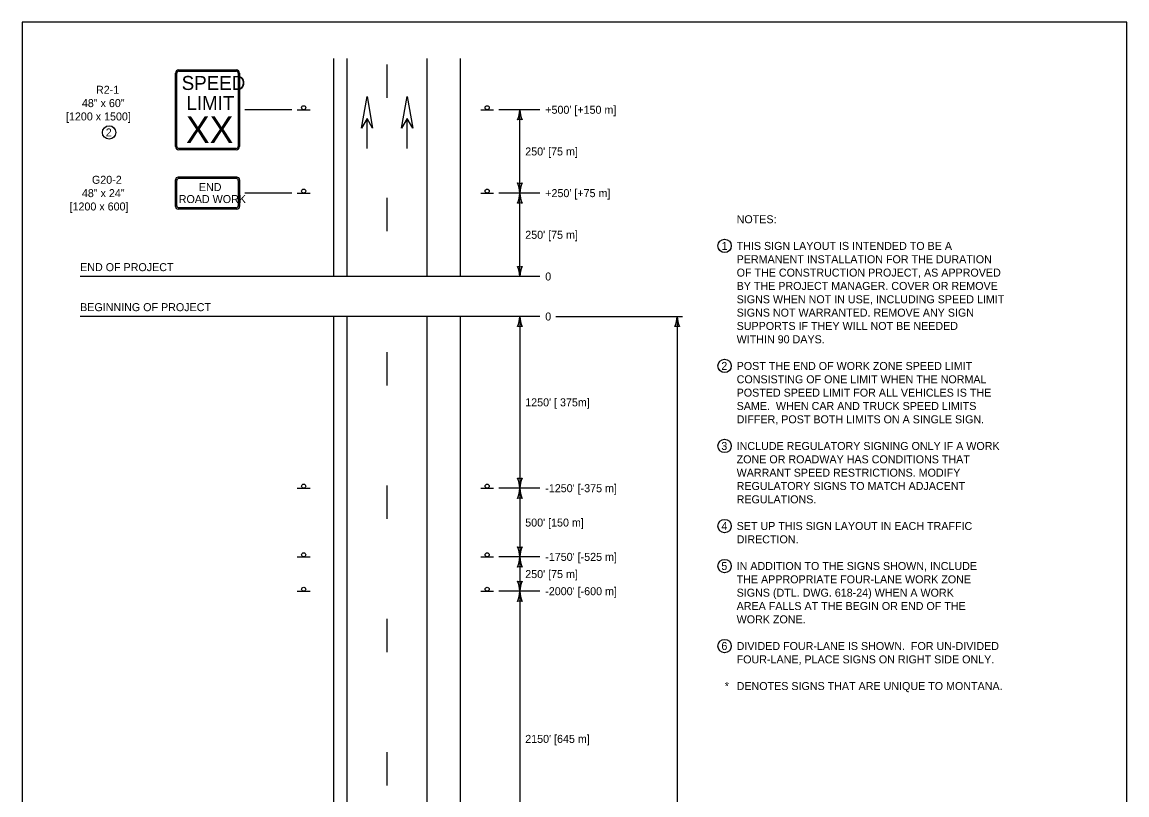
# Model space of a CAD drawing. Extents: x 49991.4 to 50021, y 49987.6 to 50011.4.
# Drawn here: x 50000.34 to 50008.61, y 50005.47 to 50011.26 of the extents above; entities that cross this region are included whole.
import ezdxf

# ---------------------------------------------------------------- set-up
doc = ezdxf.new("R2010")
doc.units = 0
for name, color, linetype in [('Level 1', 7, 'Continuous'), ('Level 2', 7, 'Continuous'), ('Level 3', 7, 'Continuous')]:
    doc.layers.add(name, color=color, linetype=linetype)

msp = doc.modelspace()

# ---------------------------------------------------------------- linework, layer by layer
at = {"layer": 'Level 1'}
for p, q in [((50002.6707, 50009.3553), (50002.6707, 50010.9901)), ((50002.7707, 50009.3553), (50002.7707, 50010.9901)), ((50003.3707, 50009.3553), (50003.3707, 50010.9901)), ((50003.6207, 50009.3553), (50003.6207, 50010.9901)), ((50001.4852, 50010.3303), (50001.4852, 50010.8803)), ((50001.4952, 50010.3303), (50001.4952, 50010.8803)), ((50001.5102, 50010.9053), (50001.9402, 50010.9053)), ((50001.5102, 50010.8953), (50001.9402, 50010.8953)), ((50001.9552, 50010.8803), (50001.9552, 50010.3303)), ((50001.9652, 50010.8803), (50001.9652, 50010.3303)), ((50003.0707, 50010.6959), (50003.0707, 50010.9459)), ((50002.3977, 50010.6053), (50002.4937, 50010.6053)), ((50003.7727, 50010.6053), (50003.8687, 50010.6053)), ((50002.9207, 50010.3139), (50002.9207, 50010.5398)), ((50002.921, 50010.3139), (50002.921, 50010.5398)), ((50003.2207, 50010.3139), (50003.2207, 50010.5398)), ((50003.221, 50010.3139), (50003.221, 50010.5398)), ((50001.9402, 50010.3153), (50001.5102, 50010.3153)), ((50001.9402, 50010.3053), (50001.5102, 50010.3053)), ((50001.4852, 50009.8803), (50001.4852, 50010.0803)), ((50001.4952, 50009.8853), (50001.4952, 50010.0753)), ((50001.9452, 50010.1003), (50001.5052, 50010.1003)), ((50001.9402, 50010.0903), (50001.5102, 50010.0903)), ((50001.9552, 50010.0753), (50001.9552, 50009.8853)), ((50001.9652, 50010.0803), (50001.9652, 50009.8803)), ((50002.3977, 50009.9803), (50002.4937, 50009.9803)), ((50003.7727, 50009.9803), (50003.8687, 50009.9803)), ((50003.0707, 50009.6959), (50003.0707, 50009.9459)), ((50001.9452, 50009.8603), (50001.5052, 50009.8603)), ((50001.9402, 50009.8703), (50001.5102, 50009.8703)), ((50002.6707, 50000.3351), (50002.6707, 50009.0553)), ((50002.7707, 50000.3351), (50002.7707, 50009.0553)), ((50003.3707, 50000.3351), (50003.3707, 50009.0553)), ((50003.6207, 50000.3351), (50003.6207, 50009.0553)), ((50003.0707, 50008.5379), (50003.0707, 50008.7879)), ((50002.3977, 50007.7678), (50002.4937, 50007.7678)), ((50003.0707, 50007.5379), (50003.0707, 50007.7879)), ((50003.7727, 50007.7678), (50003.8687, 50007.7678)), ((50002.3977, 50007.2528), (50002.4937, 50007.2528)), ((50003.7727, 50007.2528), (50003.8687, 50007.2528)), ((50002.3977, 50006.9953), (50002.4937, 50006.9953)), ((50003.7727, 50006.9953), (50003.8687, 50006.9953)), ((50003.0707, 50006.5379), (50003.0707, 50006.7879)), ((50003.0707, 50005.5379), (50003.0707, 50005.7879))]:
    msp.add_line(p, q, dxfattribs=at)
for points in [[(50008.6146, 50011.2628), (50000.3356, 50011.2628), (50000.3356, 50000.0624), (50008.6146, 50000.0624)], [(50002.879, 50010.4675), (50002.9207, 50010.704), (50002.9626, 50010.4675), (50002.9207, 50010.5397)], [(50003.179, 50010.4675), (50003.2207, 50010.704), (50003.2626, 50010.4675), (50003.2207, 50010.5397)]]:
    msp.add_lwpolyline(points, close=True, dxfattribs=at)
for centre in [(50002.4457, 50010.6205), (50003.8207, 50010.6205), (50002.4457, 50009.9955), (50003.8207, 50009.9955), (50002.4457, 50007.783), (50003.8207, 50007.783), (50002.4457, 50007.268), (50003.8207, 50007.268), (50002.4457, 50007.0105), (50003.8207, 50007.0105)]:
    msp.add_circle(centre, 0.0152, dxfattribs=at)
for centre, radius, start, end in [((50001.5102, 50010.8803), 0.025, 90, 180), ((50001.5102, 50010.8803), 0.015, 90, 180), ((50001.9402, 50010.8803), 0.025, 0, 90), ((50001.9402, 50010.8803), 0.015, 0, 90), ((50001.5102, 50010.3303), 0.025, 180, 270), ((50001.5102, 50010.3303), 0.015, 180, 270), ((50001.9402, 50010.3303), 0.025, 270, 0), ((50001.9402, 50010.3303), 0.015, 270, 0), ((50001.5052, 50010.0803), 0.02, 90, 180), ((50001.5102, 50010.0753), 0.015, 90, 180), ((50001.9402, 50010.0753), 0.015, 0, 90), ((50001.9452, 50010.0803), 0.02, 0, 90), ((50001.5051, 50009.8803), 0.02, 180, 270), ((50001.5102, 50009.8853), 0.015, 180, 270), ((50001.9402, 50009.8853), 0.015, 270, 0), ((50001.9451, 50009.8803), 0.02, 270, 0)]:
    msp.add_arc(centre, radius, start, end, dxfattribs=at)
at = {"layer": 'Level 2'}
for centre in [(50000.9877, 50010.4353), (50005.6002, 50009.5844), (50005.6002, 50008.6845), (50005.6002, 50008.0844), (50005.6002, 50007.4844), (50005.6002, 50007.1844), (50005.6002, 50006.5844)]:
    msp.add_circle(centre, 0.05, dxfattribs=at)
at = {"layer": 'Level 3'}
for p, q in [((50002.3577, 50010.6053), (50002.0052, 50010.6053)), ((50004.2159, 50010.6053), (50003.9087, 50010.6053)), ((50004.0659, 50009.9803), (50004.0659, 50010.6053)), ((50002.3577, 50009.9803), (50002.0052, 50009.9803)), ((50004.2159, 50009.9803), (50003.9087, 50009.9803)), ((50004.0659, 50009.3553), (50004.0659, 50009.9803)), ((50004.2159, 50009.3553), (50000.7705, 50009.3553)), ((50004.2159, 50009.0553), (50000.7705, 50009.0553)), ((50004.0656, 50009.0553), (50004.0659, 50008.5553)), ((50004.3358, 50009.0553), (50005.2845, 50009.0553)), ((50005.2445, 50009.0553), (50005.2445, 50001.0222)), ((50004.0659, 50008.5553), (50004.0659, 50007.7678)), ((50004.2159, 50007.7678), (50003.9087, 50007.7678)), ((50004.0659, 50007.7678), (50004.0659, 50007.2528)), ((50004.2159, 50007.2528), (50003.9087, 50007.2528)), ((50004.0659, 50007.2528), (50004.0659, 50006.9953)), ((50004.2159, 50006.9953), (50003.9087, 50006.9953)), ((50004.0659, 50006.9953), (50004.0659, 50004.7808))]:
    msp.add_line(p, q, dxfattribs=at)
for centre, radius, start, end in [((50003.8332, 50010.6168), 0.233, 337.92284, 357.17269), ((50004.288, 50010.6145), 0.2223, 182.36048, 202.54399), ((50004.0659, 50010.4771), 0.0548, 72.13882, 107.86118), ((50003.8437, 50009.9711), 0.2223, 2.36048, 22.54399), ((50004.0659, 50010.1085), 0.0548, 252.13882, 287.86118), ((50004.2986, 50009.9688), 0.233, 157.92284, 177.17269), ((50003.8332, 50009.9918), 0.233, 337.92284, 357.17269), ((50004.288, 50009.9895), 0.2223, 182.36048, 202.54399), ((50004.0659, 50009.8521), 0.0548, 72.13882, 107.86118), ((50003.8437, 50009.3461), 0.2223, 2.36048, 22.54399), ((50004.0659, 50009.4835), 0.0548, 252.13882, 287.86118), ((50004.2986, 50009.3438), 0.233, 157.92284, 177.17269), ((50003.8434, 50009.0645), 0.2223, 337.45601, 357.63952), ((50004.2983, 50009.0668), 0.233, 182.82731, 202.07716), ((50005.0224, 50009.0645), 0.2223, 337.45601, 357.63952), ((50005.4772, 50009.0668), 0.233, 182.82731, 202.07716), ((50004.0656, 50008.9271), 0.0548, 72.13882, 107.86118), ((50005.2445, 50008.9271), 0.0548, 72.13882, 107.86118), ((50004.0659, 50007.896), 0.0548, 252.13882, 287.86118), ((50003.8332, 50007.7563), 0.233, 2.82731, 22.07716), ((50004.288, 50007.7586), 0.2223, 157.45601, 177.63952), ((50003.8437, 50007.777), 0.2223, 337.45601, 357.63952), ((50004.2986, 50007.7793), 0.233, 182.82731, 202.07716), ((50004.0659, 50007.6396), 0.0548, 72.13882, 107.86118), ((50004.0659, 50007.381), 0.0548, 252.13882, 287.86118), ((50003.8332, 50007.2413), 0.233, 2.82731, 22.07716), ((50004.288, 50007.2436), 0.2223, 157.45601, 177.63952), ((50003.8437, 50007.262), 0.2223, 337.45601, 357.63952), ((50004.2986, 50007.2643), 0.233, 182.82731, 202.07716), ((50004.0659, 50007.1246), 0.0548, 72.13882, 107.86118), ((50004.0659, 50007.1235), 0.0548, 252.13882, 287.86118), ((50003.8332, 50006.9838), 0.233, 2.82731, 22.07716), ((50004.288, 50006.9861), 0.2223, 157.45601, 177.63952), ((50003.8437, 50007.0045), 0.2223, 337.45601, 357.63952), ((50004.2986, 50007.0068), 0.233, 182.82731, 202.07716), ((50004.0659, 50006.8671), 0.0548, 72.13882, 107.86118)]:
    msp.add_arc(centre, radius, start, end, dxfattribs=at)

# ---------------------------------------------------------------- texts
at = {"layer": 'Level 1'}
for s, height, p in [('SPEED', 0.10512, (50001.5314, 50010.7537)), ('LIMIT', 0.10512, (50001.5668, 50010.6036)), ('XX', 0.19892, (50001.5636, 50010.3563)), ('END', 0.06, (50001.6602, 50009.9958)), ('ROAD WORK', 0.06, (50001.5094, 50009.9058))]:
    msp.add_text(s, height=height, dxfattribs=at).set_placement(p)
at = {"layer": 'Level 2'}
for s, p in [('R2-1', (50000.8894, 50010.7253)), ('48" x 60"', (50000.7838, 50010.6253)), ("+500' [+150 m]", (50004.2559, 50010.5753)), ('[1200 x 1500]', (50000.6644, 50010.5253)), ('2', (50000.9625, 50010.4053)), ("250' [75 m]", (50004.1059, 50010.2628)), ('G20-2', (50000.8591, 50010.0503)), ('48" x 24"', (50000.7838, 50009.9503)), ("+250' [+75 m]", (50004.2559, 50009.9503)), ('[1200 x 600]', (50000.6913, 50009.8503)), ('NOTES:', (50005.6902, 50009.7544)), ("250' [75 m]", (50004.1059, 50009.6378)), ('1', (50005.5777, 50009.5545)), ('THIS SIGN LAYOUT IS INTENDED TO BE A', (50005.6902, 50009.5544)), ('PERMANENT INSTALLATION FOR THE DURATION', (50005.6902, 50009.4544)), ('END OF PROJECT', (50000.7705, 50009.3953)), ('0', (50004.2559, 50009.3253)), ('OF THE CONSTRUCTION PROJECT, AS APPROVED', (50005.6902, 50009.3544)), ('BY THE PROJECT MANAGER. COVER OR REMOVE ', (50005.6902, 50009.2544)), ('BEGINNING OF PROJECT', (50000.7705, 50009.0953)), ('SIGNS WHEN NOT IN USE, INCLUDING SPEED LIMIT ', (50005.6902, 50009.1544)), ('0', (50004.2559, 50009.0253)), ('SIGNS NOT WARRANTED. REMOVE ANY SIGN ', (50005.6902, 50009.0544)), ('SUPPORTS IF THEY WILL NOT BE NEEDED ', (50005.6902, 50008.9544)), ('WITHIN 90 DAYS.', (50005.6902, 50008.8544)), ('2', (50005.5752, 50008.6546)), ('POST THE END OF WORK ZONE SPEED LIMIT', (50005.6902, 50008.6544)), ('CONSISTING OF ONE LIMIT WHEN THE NORMAL', (50005.6902, 50008.5544)), ('POSTED SPEED LIMIT FOR ALL VEHICLES IS THE', (50005.6902, 50008.4544)), ("1250' [ 375m]", (50004.1059, 50008.3816)), ('SAME.  WHEN CAR AND TRUCK SPEED LIMITS ', (50005.6902, 50008.3544)), ('DIFFER, POST BOTH LIMITS ON A SINGLE SIGN.', (50005.6902, 50008.2544)), ('3', (50005.5751, 50008.0545)), ('INCLUDE REGULATORY SIGNING ONLY IF A WORK ', (50005.6902, 50008.0544)), ('ZONE OR ROADWAY HAS CONDITIONS THAT ', (50005.6902, 50007.9544)), ('WARRANT SPEED RESTRICTIONS. MODIFY ', (50005.6902, 50007.8544)), ('REGULATORY SIGNS TO MATCH ADJACENT ', (50005.6902, 50007.7544)), ("-1250' [-375 m]", (50004.2559, 50007.7378)), ('REGULATIONS.', (50005.6902, 50007.6544)), ("500' [150 m]", (50004.1059, 50007.4803)), ('4', (50005.5763, 50007.4545)), ('SET UP THIS SIGN LAYOUT IN EACH TRAFFIC', (50005.6902, 50007.4544)), ('DIRECTION.', (50005.6902, 50007.3544)), ("-1750' [-525 m]", (50004.2559, 50007.2228)), ("250' [75 m]", (50004.1059, 50007.094)), ('5', (50005.5754, 50007.1545)), ('IN ADDITION TO THE SIGNS SHOWN, INCLUDE', (50005.6902, 50007.1544)), ('THE APPROPRIATE FOUR-LANE WORK ZONE', (50005.6902, 50007.0544)), ("-2000' [-600 m]", (50004.2559, 50006.9653)), ('SIGNS (DTL. DWG. 618-24) WHEN A WORK ', (50005.6902, 50006.9544)), ('AREA FALLS AT THE BEGIN OR END OF THE ', (50005.6902, 50006.8544)), ('WORK ZONE.', (50005.6902, 50006.7544)), ('6', (50005.5758, 50006.5545)), ('DIVIDED FOUR-LANE IS SHOWN.  FOR UN-DIVIDED', (50005.6902, 50006.5544)), ('FOUR-LANE, PLACE SIGNS ON RIGHT SIDE ONLY.', (50005.6902, 50006.4544)), ('*', (50005.601, 50006.2544)), ('DENOTES SIGNS THAT ARE UNIQUE TO MONTANA.', (50005.6902, 50006.2544)), ("2150' [645 m]", (50004.1059, 50005.8581))]:
    msp.add_text(s, height=0.06, dxfattribs=at).set_placement(p)

doc.saveas('drawing.dxf')
